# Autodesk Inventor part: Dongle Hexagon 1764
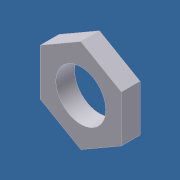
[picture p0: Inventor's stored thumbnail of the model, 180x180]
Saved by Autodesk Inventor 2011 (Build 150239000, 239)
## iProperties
Created: 2010-01
Part Number: Dongle Hexagon 1764
Document SubType Name: Modeling
Designer: jgehrig
Density: 1 g/cm^3
Author: jgehrig
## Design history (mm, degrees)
sketch "Sketch1"
  geometry: L1 (0, 4.766)-(4.127, 2.383); L2 (4.127, 2.383)-(4.128, -2.383); L3 (4.128, -2.383)-(0, -4.766); L4 (0, -4.766)-(-4.128, -2.383); L5 (-4.128, -2.383)-(-4.128, 2.383); L6 (-4.128, 2.383)-(0, 4.766); C1 r 2.54 at (0, 0); 2 further points
  constraints: 12 end point, 2 coincident, 1 centre point, 13 other
  dimensions: "d0" = 8.255 distance between parallel lines of L2 L5; "d1" = 5.08 diameter of C1
extrude "Extrusion1" new body sketch "Sketch1" distance "d2" = 1.905; taper "d3" = 0 deg
body "Solid1"
